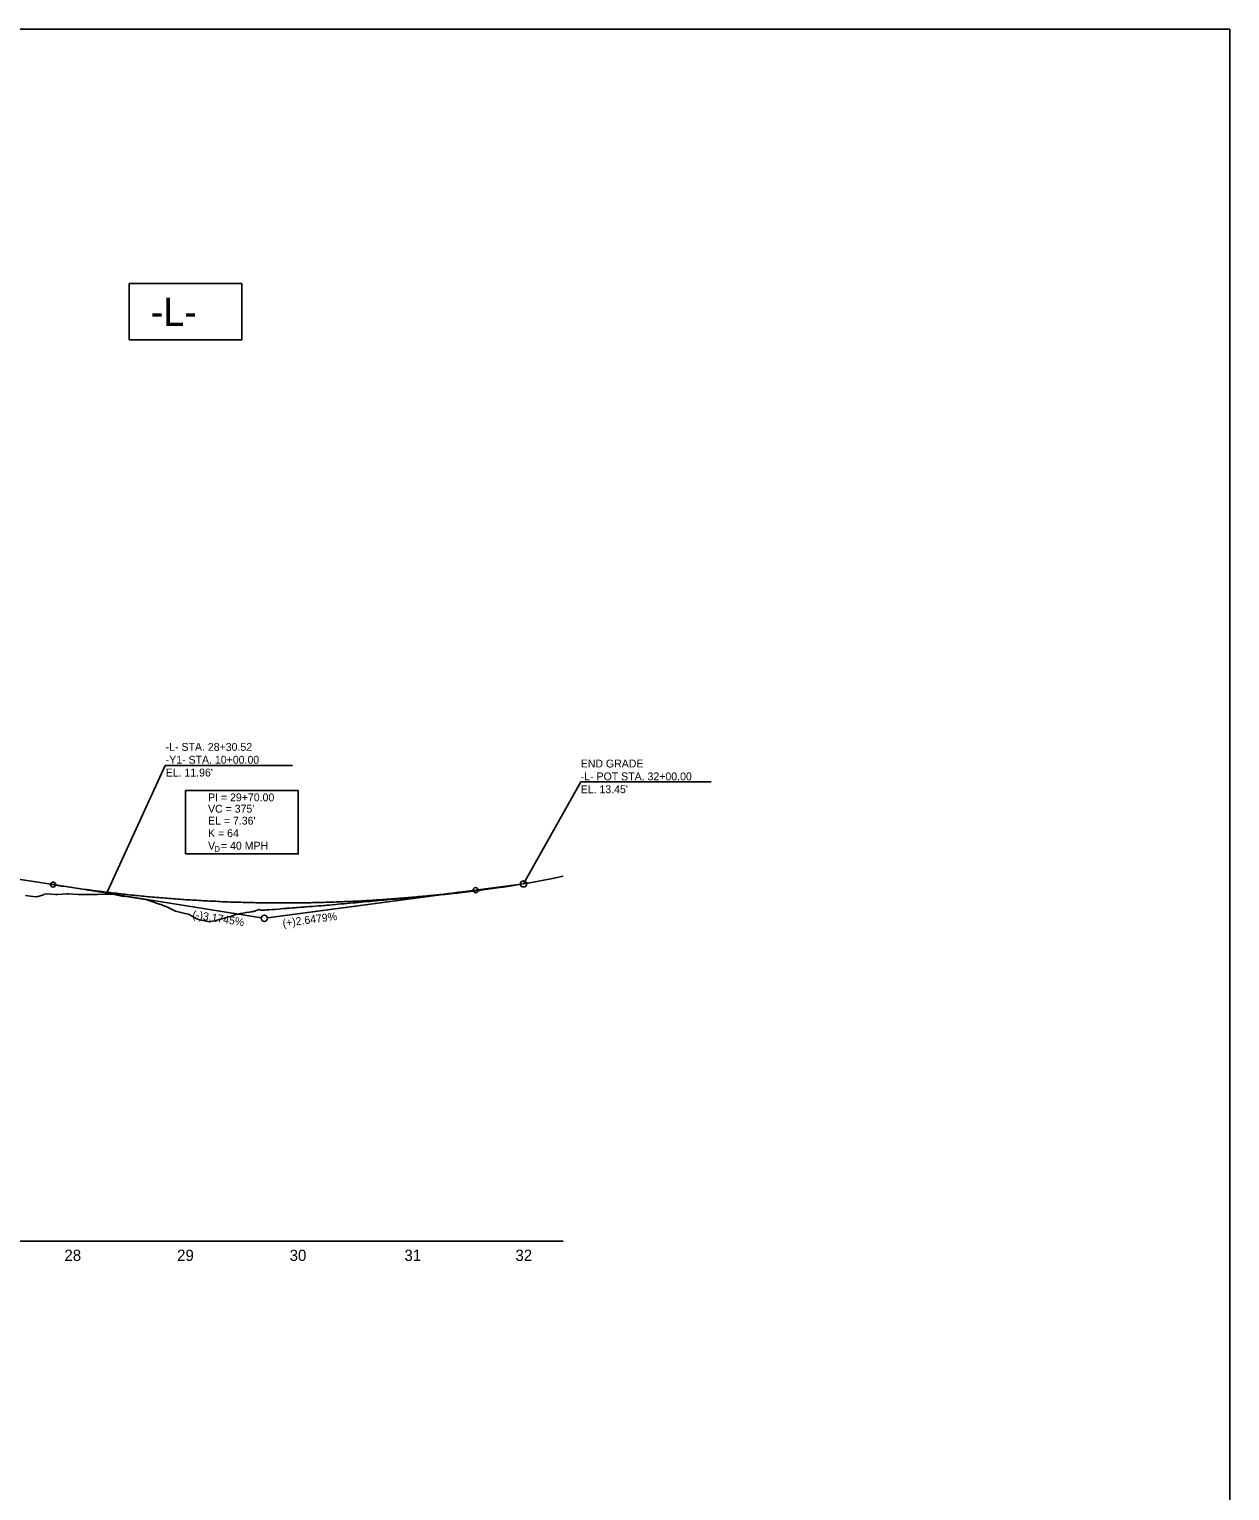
# Model space of a CAD drawing. Extents: x 1626634 to 1638383, y 876896 to 886347.
# Drawn here: x 1629329 to 1630395, y 879589 to 880886 of the extents above; entities that cross this region are included whole.
import ezdxf

# ---------------------------------------------------------------- set-up
doc = ezdxf.new("R2010")
doc.units = 0
for name, color, linetype in [('Exist Profile Cell', 7, 'Continuous'), ('Exist Vertical Profile Ground Line', 7, 'Continuous'), ('Exist Vertical Profile Horizontal Axis Label Major', 7, 'Continuous'), ('Prop Vertical Profile Curve Label', 7, 'Continuous'), ('Prop Vertical Profile Grade', 7, 'Continuous'), ('Prop Vertical Profile Grade Label', 7, 'Continuous'), ('Prop VPI Label', 7, 'Continuous')]:
    doc.layers.add(name, color=color, linetype=linetype)

msp = doc.modelspace()

# ---------------------------------------------------------------- linework, layer by layer
at = {"layer": 'Exist Profile Cell'}
msp.add_line((1627567.6, 879810.5), (1629802.7, 879810.5), dxfattribs=at)
at = {"layer": 'Exist Vertical Profile Ground Line'}
msp.add_lwpolyline([(1629325.7, 880117.5), (1629332.2, 880116.5), (1629335.7, 880116.3), (1629341.5, 880118), (1629342.2, 880118.7), (1629344.6, 880119), (1629352.2, 880118.3), (1629354.1, 880118.3), (1629362.2, 880118.8), (1629363.6, 880118.9), (1629372.2, 880118.3), (1629373.1, 880118.2), (1629374.8, 880118.2), (1629383.8, 880118.3), (1629389.6, 880118.3), (1629402, 880118.7), (1629403.1, 880118.6), (1629412.4, 880116.6), (1629413.2, 880116.7), (1629429.9, 880114.2), (1629432.3, 880113.7), (1629439.4, 880111.6), (1629442.3, 880110.3), (1629445.6, 880109.5), (1629452.3, 880106.7), (1629456.2, 880104.8), (1629458.8, 880103.4), (1629467, 880101.5), (1629468.5, 880101), (1629470.1, 880100.8), (1629477.5, 880096.7), (1629479, 880096), (1629489, 880094), (1629494.5, 880095.3), (1629498.8, 880096.4), (1629505.8, 880098.5), (1629508.6, 880099), (1629510.4, 880099.9), (1629515.5, 880101.2), (1629516.4, 880101.3), (1629517.3, 880101.5), (1629518.9, 880101.8), (1629521.5, 880102.2), (1629524, 880102.6), (1629525.8, 880102.9), (1629526.6, 880103), (1629527, 880103.1), (1629527.5, 880103.1), (1629528.1, 880103.2), (1629529.1, 880103.6), (1629531.7, 880104.7), (1629532.6, 880105), (1629534.2, 880104.5), (1629534.8, 880104.3), (1629536.8, 880104.4), (1629537.2, 880104.4), (1629537.9, 880104.5), (1629539.3, 880104.6), (1629541.9, 880104.8), (1629544.5, 880104.9), (1629547, 880105.1), (1629549.8, 880105.3), (1629552.1, 880105.5), (1629554.7, 880105.7), (1629557.2, 880105.9), (1629557.9, 880106), (1629559.8, 880106.1), (1629562.3, 880106.3), (1629564.9, 880106.5), (1629566, 880106.6), (1629567.4, 880106.7), (1629570, 880106.9), (1629572.5, 880107.1), (1629574.1, 880107.2), (1629575.1, 880107.3), (1629577.7, 880107.5), (1629580.2, 880107.7), (1629582.8, 880107.9), (1629585.3, 880108.1), (1629586.8, 880108.2), (1629587.9, 880108.3), (1629590.4, 880108.5), (1629591.5, 880108.6), (1629593, 880108.7), (1629595.5, 880108.9), (1629598.1, 880109.2), (1629600.6, 880109.4), (1629603.2, 880109.6), (1629605.7, 880109.9), (1629606.5, 880109.9), (1629607.9, 880110), (1629608.3, 880110.1), (1629610.8, 880110.3), (1629613.4, 880110.5), (1629616, 880110.8), (1629618.5, 880111), (1629621.1, 880111.3), (1629623.6, 880111.5), (1629625.7, 880111.7), (1629626.2, 880111.7), (1629628.7, 880112), (1629631.3, 880112.2), (1629633.8, 880112.4), (1629636.4, 880112.7), (1629637.1, 880112.7), (1629638.9, 880112.9), (1629641.5, 880113.1), (1629644, 880113.3), (1629645.2, 880113.4), (1629645.8, 880113.4), (1629646.6, 880113.5), (1629649.1, 880113.7), (1629651.7, 880114), (1629654.3, 880114.2), (1629656.8, 880114.4), (1629659.4, 880114.6), (1629661.9, 880114.8), (1629664.5, 880115.1), (1629665.2, 880115.1), (1629667, 880115.3), (1629669.6, 880115.6), (1629672.1, 880115.8), (1629674.7, 880116.1), (1629677.2, 880116.4), (1629679.8, 880116.6), (1629682.3, 880116.8), (1629684.9, 880117.1), (1629686.7, 880117.3), (1629687, 880117.3), (1629687.4, 880117.3), (1629690, 880117.6), (1629692.6, 880117.9), (1629695.1, 880118.2), (1629697.7, 880118.4), (1629700.2, 880118.7), (1629702.8, 880119), (1629705.3, 880119.2), (1629707.9, 880119.5), (1629708.8, 880119.6), (1629709.1, 880119.6), (1629710.4, 880119.8), (1629713, 880120.1), (1629715.5, 880120.4), (1629718.1, 880120.7), (1629720.6, 880121), (1629723.2, 880121.3), (1629725.7, 880121.6), (1629728.8, 880121.9), (1629729.5, 880122), (1629748.8, 880124.7), (1629749.8, 880124.8), (1629771, 880128.2), (1629771.7, 880128.3), (1629793.3, 880132.5), (1629802.7, 880134.4)], dxfattribs=at)
at = {"layer": 'Prop Vertical Profile Curve Label'}
msp.add_lwpolyline([(1626634.5, 880886.3), (1630394.5, 880886.3), (1630394.5, 878291.7), (1626634.5, 878291.7)], close=True, dxfattribs=at)
for centre in [(1629350.1, 880127), (1629725.1, 880122.1)]:
    msp.add_circle(centre, 2.25, dxfattribs=at)
at = {"layer": 'Prop Vertical Profile Grade'}
for p, q in [((1629307.6, 880133.7), (1629350.1, 880127)), ((1629725.1, 880122.1), (1629767.6, 880127.7))]:
    msp.add_line(p, q, dxfattribs=at)
msp.add_spline([(1629350.1, 880127), (1629357.6, 880125.8), (1629365.1, 880124.7), (1629372.6, 880123.6), (1629380.1, 880122.6), (1629387.6, 880121.6), (1629395.1, 880120.6), (1629402.6, 880119.7), (1629410.1, 880118.9), (1629417.6, 880118), (1629425.1, 880117.3), (1629432.6, 880116.5), (1629440.1, 880115.9), (1629447.6, 880115.2), (1629455.1, 880114.6), (1629462.6, 880114.1), (1629470.1, 880113.5), (1629477.6, 880113.1), (1629485.1, 880112.6), (1629492.6, 880112.3), (1629500.1, 880111.9), (1629507.6, 880111.6), (1629515.1, 880111.4), (1629522.6, 880111.2), (1629530.1, 880111), (1629537.6, 880110.9), (1629545.1, 880110.8), (1629552.6, 880110.8), (1629560.1, 880110.8), (1629567.6, 880110.8), (1629575.1, 880110.9), (1629582.6, 880111.1), (1629590.1, 880111.3), (1629597.6, 880111.5), (1629605.1, 880111.8), (1629612.6, 880112.1), (1629620.1, 880112.4), (1629627.6, 880112.8), (1629635.1, 880113.3), (1629642.6, 880113.8), (1629650.1, 880114.3), (1629657.6, 880114.9), (1629665.1, 880115.5), (1629672.6, 880116.2), (1629680.1, 880116.9), (1629687.6, 880117.6), (1629695.1, 880118.4), (1629702.6, 880119.3), (1629710.1, 880120.2), (1629717.6, 880121.1), (1629725.1, 880122.1)], degree=3, dxfattribs=at)
at = {"layer": 'Prop VPI Label'}
for p, q in [((1629398.1, 880120.3), (1629449.6, 880232.8)), ((1629562.7, 880232.8), (1629449.6, 880232.8)), ((1629767.6, 880127.7), (1629818.4, 880218.4)), ((1629934.2, 880218.4), (1629818.4, 880218.4)), ((1629350.1, 880127), (1629534.9, 880097.7)), ((1629767.6, 880127.7), (1629540.4, 880097.6)), ((1629725.1, 880122.1), (1629540.4, 880097.6))]:
    msp.add_line(p, q, dxfattribs=at)
for points in [[(1629417.6, 880660.5), (1629517.6, 880660.5), (1629517.6, 880610.5), (1629417.6, 880610.5)], [(1629417.6, 880660.5), (1629517.6, 880660.5), (1629517.6, 880610.5), (1629417.6, 880610.5)], [(1629417.6, 880660.5), (1629517.6, 880660.5), (1629517.6, 880610.5), (1629417.6, 880610.5)], [(1629417.6, 880660.5), (1629517.6, 880660.5), (1629517.6, 880610.5), (1629417.6, 880610.5)], [(1629467.6, 880210.5), (1629567.6, 880210.5), (1629567.6, 880154.3), (1629467.6, 880154.3)], [(1629467.6, 880210.5), (1629567.6, 880210.5), (1629567.6, 880154.3), (1629467.6, 880154.3)]]:
    msp.add_lwpolyline(points, close=True, dxfattribs=at)
for centre in [(1629767.6, 880127.7), (1629767.6, 880127.7), (1629767.6, 880127.7), (1629537.6, 880097.2)]:
    msp.add_circle(centre, 2.75, dxfattribs=at)

# ---------------------------------------------------------------- texts
at = {"layer": 'Exist Vertical Profile Horizontal Axis Label Major'}
for s, p in [('28', (1629360.1, 879793)), ('29', (1629460.1, 879793)), ('30', (1629560, 879793)), ('31', (1629661.9, 879793)), ('32', (1629760.4, 879793))]:
    msp.add_text(s, height=10, dxfattribs=at).set_placement(p)
at = {"layer": 'Prop Vertical Profile Curve Label'}
for s, height, p in [('-L-', 25, (1629436.7, 880623)), ("VC = 375'", 7, (1629487.6, 880190.9)), ('K = 64', 7, (1629487.6, 880169.2))]:
    msp.add_text(s, height=height, dxfattribs=at).set_placement(p)
for s, height, p in [('V  = 40 MPH', 7, (1629487.6, 880158.1)), ('D', 5.25, (1629493.1, 880156.1))]:
    msp.add_text(s, height=height, rotation=360, dxfattribs=at).set_placement(p)
at = {"layer": 'Prop Vertical Profile Grade Label'}
for s, rotation, p in [('(-)3.1745%', 350.981, (1629473.4, 880097.3)), ('(+)2.6479%', 7.5417, (1629554.2, 880089.3))]:
    msp.add_text(s, height=7, rotation=rotation, dxfattribs=at).set_placement(p)
at = {"layer": 'Prop VPI Label'}
for s, p in [('-L- STA. 28+30.52', (1629450, 880245.8)), ('-Y1- STA. 10+00.00', (1629450, 880234.4)), ("EL. 11.96'", (1629450, 880223)), ('END GRADE', (1629818.4, 880231)), ('-L- POT STA. 32+00.00', (1629818.4, 880219.6)), ("EL. 13.45'", (1629818.4, 880208.2)), ('PI = 29+70.00', (1629487.6, 880201)), ("EL = 7.36'", (1629487.6, 880180.3))]:
    msp.add_text(s, height=7, dxfattribs=at).set_placement(p)

doc.saveas('drawing.dxf')
